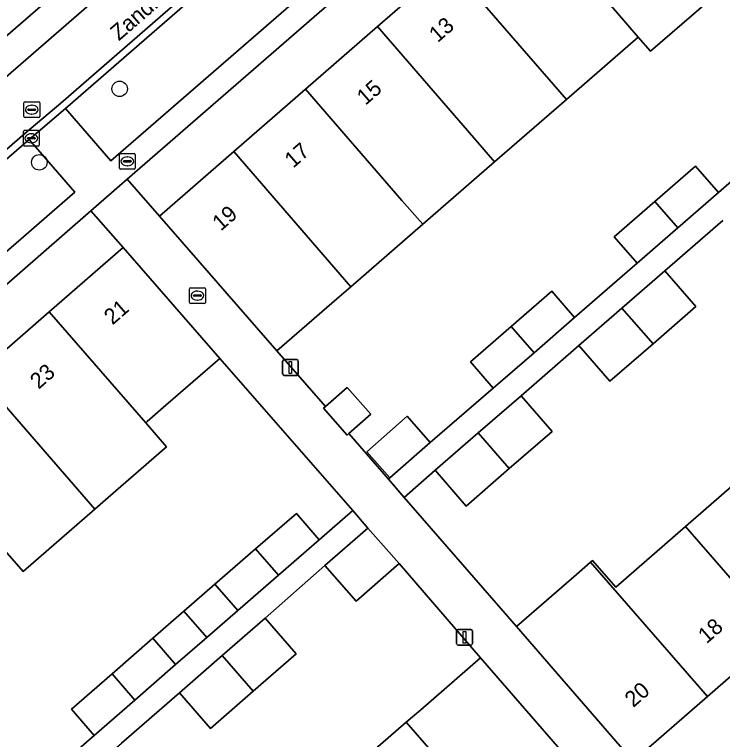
# Model space of a CAD drawing. Extents: x 155887 to 156869, y 383880 to 384678.
# Drawn here: x 156410.69 to 156455.35, y 384008.68 to 384054.39 of the extents above; entities that cross this region are included whole.
import ezdxf

# ---------------------------------------------------------------- set-up
doc = ezdxf.new("R2010")
doc.units = 0
for name, color, linetype in [('IMGEO_Boom', 7, 'Continuous'), ('IMGEO_Brandkraan', 7, 'Continuous'), ('IMGEO_Erf', 7, 'Continuous'), ('IMGEO_Kolk', 7, 'Continuous'), ('IMGEO_Lichtmast', 7, 'Continuous'), ('IMGEO_Openbare_ruimte_label', 7, 'Continuous'), ('IMGEO_Pand', 7, 'Continuous'), ('IMGEO_Pand_nummerreeks', 7, 'Continuous'), ('IMGEO_Parkeervlak_open', 7, 'Continuous'), ('IMGEO_Rijbaan_lokaal_gesloten', 7, 'Continuous'), ('IMGEO_Rijbaan_lokaal_open', 7, 'Continuous'), ('IMGEO_Rioolput', 7, 'Continuous'), ('IMGEO_Voetpad_open', 7, 'Continuous')]:
    doc.layers.add(name, color=color, linetype=linetype)

msp = doc.modelspace()

# ---------------------------------------------------------------- linework, layer by layer
at = {"layer": 'IMGEO_Boom'}
for centre in [(156417.316, 384049.703), (156412.249, 384045.068)]:
    msp.add_circle(centre, 0.489, dxfattribs=at)
at = {"layer": 'IMGEO_Brandkraan'}
for p, q in [((156417.303, 384044.707), (156417.303, 384045.559)), ((156417.378, 384045.633), (156418.23, 384045.633)), ((156417.791, 384045.413), (156417.816, 384045.413)), ((156418.304, 384045.559), (156418.304, 384044.707)), ((156417.562, 384045.127), (156417.562, 384045.139)), ((156418, 384045.09), (156417.602, 384045.09)), ((156417.605, 384045.176), (156418.003, 384045.176)), ((156417.814, 384044.853), (156417.789, 384044.853)), ((156418.046, 384045.139), (156418.046, 384045.127)), ((156418.23, 384044.633), (156417.378, 384044.633))]:
    msp.add_line(p, q, dxfattribs=at)
for points in [[(156417.303, 384044.707), (156417.303, 384045.559)], [(156417.378, 384045.633), (156418.23, 384045.633)], [(156418.304, 384045.559), (156418.304, 384044.707)], [(156418.23, 384044.633), (156417.378, 384044.633)]]:
    msp.add_lwpolyline(points, dxfattribs=at)
for centre, radius, start, end in [((156417.38, 384045.557), 0.0765, 91.552, 178.448), ((156417.38, 384045.557), 0.0765, 91.552, 178.448), ((156418.228, 384045.557), 0.0765, 1.552, 88.448), ((156418.228, 384045.557), 0.0765, 1.552, 88.448), ((156417.602, 384045.136), 0.0403, 85.8775, 175.7526), ((156417.599, 384045.126), 0.0366, 178.938, 274.7102), ((156418.003, 384045.133), 0.043, 264.8664, 352.4533), ((156418.007, 384045.138), 0.0386, 1.7309, 96.639), ((156417.38, 384044.709), 0.0765, 181.552, 268.448), ((156417.38, 384044.709), 0.0765, 181.552, 268.448), ((156418.228, 384044.709), 0.0765, 271.552, 358.448), ((156418.228, 384044.709), 0.0765, 271.552, 358.448)]:
    msp.add_arc(centre, radius, start, end, dxfattribs=at)
for centre, major_axis, ratio, start_param, end_param in [((156417.79, 384045.133), (-0.387, 0.002), 0.722429, 4.712389, 7.853982), ((156417.815, 384045.133), (-0.39, 0.002), 0.717154, 1.570796, 4.712389)]:
    msp.add_ellipse(centre, major_axis=major_axis, ratio=ratio, start_param=start_param, end_param=end_param, dxfattribs=at)
at = {"layer": 'IMGEO_Erf'}
for points in [[(156410.122, 384052.983), (156447.142, 384085.078), (156444.873, 384087.686), (156442.019, 384085.204), (156443.695, 384083.269), (156440.298, 384080.316), (156436.883, 384077.347), (156435.201, 384079.289), (156432.554, 384076.982), (156429.802, 384074.584), (156431.483, 384072.642), (156428.134, 384069.735), (156424.65, 384066.712), (156422.968, 384068.654), (156420.152, 384066.214), (156417.553, 384063.962), (156419.235, 384062.02), (156415.892, 384059.117), (156412.427, 384056.109), (156410.745, 384058.051), (156407.867, 384055.552)], [(156447.16, 384065.423), (156451.688, 384069.356), (156456.231, 384073.303), (156460.743, 384077.222), (156465.403, 384081.27), (156463.383, 384083.579), (156417.787, 384044.012), (156419.831, 384041.682), (156424.521, 384045.756), (156429.049, 384049.689), (156433.577, 384053.623), (156438.104, 384057.556), (156442.032, 384060.968), (156442.633, 384061.49)], [(156495.285, 384046.946), (156490.613, 384042.883), (156486.087, 384038.947), (156481.56, 384035.01), (156477.034, 384031.074), (156472.507, 384027.137), (156467.98, 384023.2), (156463.453, 384019.263), (156458.927, 384015.327), (156454.4, 384011.39), (156449.718, 384007.318), (156452.547, 384004.012), (156498.182, 384043.649)]]:
    msp.add_lwpolyline(points, close=True, dxfattribs=at)
for points in [[(156455.377, 384056.039), (156450.81, 384052.073), (156450.035, 384052.966), (156445.504, 384049.033), (156440.967, 384045.095), (156436.437, 384041.162), (156431.908, 384037.23), (156431.017, 384036.457), (156427.241, 384033.179), (156430.298, 384029.666), (156431.679, 384030.883), (156433.17, 384029.191), (156431.779, 384027.965), (156434.278, 384025.093), (156434.364, 384025.168), (156432.912, 384026.824), (156435.467, 384029.065), (156436.918, 384027.412), (156440.892, 384030.829), (156439.451, 384032.487), (156442.019, 384034.719), (156444.576, 384036.941), (156446.017, 384035.283), (156449.964, 384038.713), (156448.523, 384040.371), (156451.089, 384042.6), (156453.648, 384044.824), (156455.089, 384043.166), (156459.013, 384046.577)], [(156408.347, 384031.713), (156412.874, 384035.649), (156417.543, 384039.709), (156415.505, 384042.009), (156388.106, 384018.114)], [(156455.367, 384041.408), (156451.707, 384038.228), (156453.668, 384035.971), (156450.967, 384033.625), (156448.249, 384031.263), (156446.288, 384033.52), (156442.644, 384030.353), (156444.599, 384028.103), (156441.899, 384025.757), (156439.188, 384023.401), (156437.233, 384025.651), (156435.275, 384023.947), (156442.364, 384015.801), (156446.137, 384019.082), (156447.03, 384019.86), (156447.155, 384019.968), (156448.618, 384018.285), (156453.023, 384022.116), (156457.55, 384026.053)], [(156411.795, 384005.532), (156415.72, 384008.941), (156414.278, 384010.601), (156416.842, 384012.828), (156419.41, 384015.059), (156421.372, 384016.764), (156423.334, 384018.468), (156425.898, 384020.695), (156428.466, 384022.926), (156429.908, 384021.266), (156432.019, 384023.109), (156423.638, 384032.71), (156420.241, 384029.754), (156419.06, 384028.727), (156418.97, 384028.649), (156420.284, 384027.141), (156416.601, 384023.936), (156415.759, 384023.203), (156411.235, 384019.266), (156409.922, 384020.774)], [(156430.874, 384005.835), (156435.4, 384009.769), (156436.309, 384010.559), (156440.083, 384013.839), (156434.944, 384019.77), (156432.24, 384017.398), (156430.265, 384019.648), (156426.497, 384016.326), (156428.453, 384014.075), (156425.747, 384011.723), (156423.044, 384009.375), (156421.088, 384011.626), (156417.445, 384008.459)]]:
    msp.add_lwpolyline(points, dxfattribs=at)
at = {"layer": 'IMGEO_Kolk'}
for p, q in [((156411.248, 384046.161), (156411.248, 384047.013)), ((156411.323, 384047.087), (156412.175, 384047.087)), ((156411.736, 384046.867), (156411.761, 384046.867)), ((156412.249, 384047.013), (156412.249, 384046.161)), ((156411.507, 384046.581), (156411.507, 384046.593)), ((156411.945, 384046.544), (156411.547, 384046.544)), ((156411.55, 384046.63), (156411.948, 384046.63)), ((156411.759, 384046.307), (156411.734, 384046.307)), ((156411.991, 384046.593), (156411.991, 384046.581)), ((156412.175, 384046.087), (156411.323, 384046.087)), ((156421.727, 384036.24), (156421.727, 384037.092)), ((156421.802, 384037.166), (156422.654, 384037.166)), ((156422.728, 384037.092), (156422.728, 384036.24)), ((156421.986, 384036.66), (156421.986, 384036.672)), ((156422.424, 384036.623), (156422.026, 384036.623)), ((156422.029, 384036.709), (156422.427, 384036.709)), ((156422.215, 384036.946), (156422.24, 384036.946)), ((156422.47, 384036.672), (156422.47, 384036.66)), ((156422.654, 384036.166), (156421.802, 384036.166)), ((156422.238, 384036.386), (156422.213, 384036.386))]:
    msp.add_line(p, q, dxfattribs=at)
for points in [[(156411.248, 384046.161), (156411.248, 384047.013)], [(156411.323, 384047.087), (156412.175, 384047.087)], [(156412.249, 384047.013), (156412.249, 384046.161)], [(156412.175, 384046.087), (156411.323, 384046.087)], [(156421.727, 384036.24), (156421.727, 384037.092)], [(156421.802, 384037.166), (156422.654, 384037.166)], [(156422.728, 384037.092), (156422.728, 384036.24)], [(156422.654, 384036.166), (156421.802, 384036.166)]]:
    msp.add_lwpolyline(points, dxfattribs=at)
for centre, radius, start, end in [((156411.325, 384047.011), 0.0765, 91.552, 178.448), ((156411.325, 384047.011), 0.0765, 91.552, 178.448), ((156412.173, 384047.011), 0.0765, 1.552, 88.448), ((156412.173, 384047.011), 0.0765, 1.552, 88.448), ((156411.547, 384046.59), 0.0403, 85.8775, 175.7526), ((156411.544, 384046.58), 0.0366, 178.938, 274.7102), ((156411.948, 384046.587), 0.043, 264.8664, 352.4533), ((156411.952, 384046.592), 0.0386, 1.7309, 96.639), ((156411.325, 384046.163), 0.0765, 181.552, 268.448), ((156411.325, 384046.163), 0.0765, 181.552, 268.448), ((156412.173, 384046.163), 0.0765, 271.552, 358.448), ((156412.173, 384046.163), 0.0765, 271.552, 358.448), ((156421.804, 384037.09), 0.0765, 91.552, 178.448), ((156421.804, 384037.09), 0.0765, 91.552, 178.448), ((156422.652, 384037.09), 0.0765, 1.552, 88.448), ((156422.652, 384037.09), 0.0765, 1.552, 88.448), ((156422.026, 384036.669), 0.0403, 85.8775, 175.7526), ((156422.023, 384036.659), 0.0366, 178.938, 274.7102), ((156422.427, 384036.666), 0.043, 264.8664, 352.4533), ((156422.431, 384036.671), 0.0386, 1.7309, 96.639), ((156421.804, 384036.242), 0.0765, 181.552, 268.448), ((156421.804, 384036.242), 0.0765, 181.552, 268.448), ((156422.652, 384036.242), 0.0765, 271.552, 358.448), ((156422.652, 384036.242), 0.0765, 271.552, 358.448)]:
    msp.add_arc(centre, radius, start, end, dxfattribs=at)
for centre, major_axis, ratio, start_param, end_param in [((156411.735, 384046.587), (-0.387, 0.002), 0.722429, 4.712389, 7.853982), ((156411.76, 384046.587), (-0.39, 0.002), 0.717154, 1.570796, 4.712389), ((156422.214, 384036.666), (-0.387, 0.002), 0.722429, 4.712389, 7.853982), ((156422.239, 384036.666), (-0.39, 0.002), 0.717154, 1.570796, 4.712389)]:
    msp.add_ellipse(centre, major_axis=major_axis, ratio=ratio, start_param=start_param, end_param=end_param, dxfattribs=at)
at = {"layer": 'IMGEO_Lichtmast'}
for p, q in [((156427.6, 384031.736), (156427.6, 384032.536)), ((156427.6, 384032.536), (156427.6, 384031.736)), ((156427.7, 384032.636), (156428.49, 384032.636)), ((156428.49, 384032.636), (156427.7, 384032.636)), ((156428.59, 384032.536), (156428.59, 384031.736)), ((156428.59, 384031.736), (156428.59, 384032.536)), ((156428.49, 384031.636), (156427.7, 384031.636)), ((156427.7, 384031.636), (156428.49, 384031.636)), ((156438.678, 384015.623), (156439.468, 384015.623)), ((156439.468, 384015.623), (156438.678, 384015.623)), ((156438.578, 384014.723), (156438.578, 384015.523)), ((156438.578, 384015.523), (156438.578, 384014.723)), ((156439.568, 384015.523), (156439.568, 384014.723)), ((156439.568, 384014.723), (156439.568, 384015.523)), ((156439.468, 384014.623), (156438.678, 384014.623)), ((156438.678, 384014.623), (156439.468, 384014.623))]:
    msp.add_line(p, q, dxfattribs=at)
for points in [[(156428.02, 384032.511), (156428.17, 384032.511), (156428.17, 384031.761), (156428.02, 384031.761), (156428.02, 384032.511)], [(156438.998, 384015.498), (156439.148, 384015.498), (156439.148, 384014.748), (156438.998, 384014.748), (156438.998, 384015.498)]]:
    msp.add_lwpolyline(points, dxfattribs=at)
for centre, start, end in [((156427.7, 384032.536), 90, 180), ((156427.7, 384032.536), 90, 180), ((156428.49, 384032.536), 0, 90), ((156428.49, 384032.536), 360, 90), ((156427.7, 384031.736), 180, 270), ((156427.7, 384031.736), 180, 270), ((156428.49, 384031.736), 270, 0), ((156428.49, 384031.736), 270, 0), ((156438.678, 384015.523), 90, 180), ((156438.678, 384015.523), 90, 180), ((156439.468, 384015.523), 0, 90), ((156439.468, 384015.523), 360, 90), ((156438.678, 384014.723), 180, 270), ((156438.678, 384014.723), 180, 270), ((156439.468, 384014.723), 270, 0), ((156439.468, 384014.723), 270, 0)]:
    msp.add_arc(centre, 0.1, start, end, dxfattribs=at)
at = {"layer": 'IMGEO_Pand'}
for points in [[(156447.16, 384065.423), (156442.633, 384061.49), (156448.724, 384054.476), (156450.035, 384052.966), (156450.81, 384052.073), (156455.377, 384056.039), (156454.5, 384056.972), (156453.253, 384058.408), (156452.773, 384058.961)], [(156442.633, 384061.49), (156442.032, 384060.968), (156438.104, 384057.556), (156445.504, 384049.033), (156450.035, 384052.966), (156448.724, 384054.476)], [(156438.104, 384057.556), (156433.577, 384053.623), (156439.658, 384046.606), (156440.967, 384045.095), (156445.504, 384049.033)], [(156433.577, 384053.623), (156429.049, 384049.689), (156435.128, 384042.673), (156436.437, 384041.162), (156440.967, 384045.095), (156439.658, 384046.606)], [(156429.049, 384049.689), (156424.521, 384045.756), (156431.908, 384037.23), (156436.437, 384041.162), (156435.128, 384042.673)], [(156431.908, 384037.23), (156424.521, 384045.756), (156419.831, 384041.682), (156427.241, 384033.179), (156431.017, 384036.457)], [(156451.089, 384042.6), (156452.529, 384040.942), (156455.089, 384043.166), (156453.648, 384044.824)], [(156451.089, 384042.6), (156448.523, 384040.371), (156449.964, 384038.713), (156452.529, 384040.942)], [(156417.543, 384039.709), (156412.874, 384035.649), (156418.97, 384028.649), (156419.06, 384028.727), (156420.241, 384029.754), (156423.638, 384032.71)], [(156449.006, 384035.881), (156450.967, 384033.625), (156453.668, 384035.971), (156451.707, 384038.228)], [(156442.019, 384034.719), (156443.458, 384033.059), (156446.017, 384035.283), (156444.576, 384036.941)], [(156449.006, 384035.881), (156446.288, 384033.52), (156448.249, 384031.263), (156450.967, 384033.625)], [(156412.874, 384035.649), (156408.347, 384031.713), (156415.759, 384023.203), (156416.601, 384023.936), (156420.284, 384027.141), (156418.97, 384028.649)], [(156442.019, 384034.719), (156439.451, 384032.487), (156440.892, 384030.829), (156443.458, 384033.059)], [(156408.347, 384031.713), (156403.822, 384027.778), (156409.922, 384020.774), (156411.235, 384019.266), (156415.759, 384023.203)], [(156430.298, 384029.666), (156430.18, 384029.562), (156431.671, 384027.87), (156431.779, 384027.965), (156433.17, 384029.191), (156431.679, 384030.883)], [(156439.942, 384028.005), (156441.899, 384025.757), (156444.599, 384028.103), (156442.644, 384030.353)], [(156434.364, 384025.168), (156436.918, 384027.412), (156435.467, 384029.065), (156432.912, 384026.824)], [(156439.942, 384028.005), (156437.233, 384025.651), (156439.188, 384023.401), (156441.899, 384025.757)], [(156458.927, 384015.327), (156463.453, 384019.263), (156457.55, 384026.053), (156453.023, 384022.116)], [(156427.342, 384019.037), (156429.908, 384021.266), (156428.466, 384022.926), (156425.898, 384020.695)], [(156434.944, 384019.77), (156432.98, 384022.008), (156430.265, 384019.648), (156432.24, 384017.398)], [(156458.927, 384015.327), (156453.023, 384022.116), (156448.618, 384018.285), (156447.155, 384019.968), (156447.03, 384019.86), (156454.4, 384011.39)], [(156427.342, 384019.037), (156425.898, 384020.695), (156423.334, 384018.468), (156424.776, 384016.808)], [(156447.03, 384019.86), (156446.137, 384019.082), (156442.364, 384015.801), (156449.718, 384007.318), (156454.4, 384011.39)], [(156423.334, 384018.468), (156421.372, 384016.764), (156422.814, 384015.103), (156424.776, 384016.808)], [(156421.372, 384016.764), (156419.41, 384015.059), (156420.852, 384013.399), (156422.814, 384015.103)], [(156425.747, 384011.723), (156428.453, 384014.075), (156426.497, 384016.326), (156423.788, 384013.972)], [(156416.842, 384012.828), (156418.286, 384011.17), (156420.852, 384013.399), (156419.41, 384015.059)], [(156425.747, 384011.723), (156423.788, 384013.972), (156421.088, 384011.626), (156423.044, 384009.375)], [(156442.777, 384001.297), (156447.442, 384005.351), (156440.083, 384013.839), (156436.309, 384010.559), (156435.4, 384009.769)], [(156416.842, 384012.828), (156414.278, 384010.601), (156415.72, 384008.941), (156418.286, 384011.17)], [(156438.193, 383997.312), (156441.285, 384000), (156442.777, 384001.297), (156435.4, 384009.769), (156430.874, 384005.835), (156435.955, 384000)]]:
    msp.add_lwpolyline(points, close=True, dxfattribs=at)
at = {"layer": 'IMGEO_Parkeervlak_open'}
msp.add_lwpolyline([(156413.906, 384048.462), (156416.764, 384045.168), (156462.406, 384084.734), (156459.54, 384088.037), (156458.91, 384087.552)], close=True, dxfattribs=at)
for points in [[(156414.489, 384043.181), (156411.601, 384046.501), (156373.103, 384013.064)], [(156366.002, 384005.454), (156368.129, 384002.924), (156414.489, 384043.181)]]:
    msp.add_lwpolyline(points, dxfattribs=at)
at = {"layer": 'IMGEO_Rijbaan_lokaal_gesloten'}
for points in [[(156372.8, 384013.411), (156411.334, 384046.878), (156413.606, 384048.808), (156458.618, 384087.909), (156458.873, 384088.104), (156452.602, 384095.338)], [(156449.055, 384084.789), (156448.166, 384083.918), (156444.013, 384079.846), (156371.934, 384017.308)]]:
    msp.add_lwpolyline(points, dxfattribs=at)
at = {"layer": 'IMGEO_Rijbaan_lokaal_open'}
for points in [[(156452.947, 384095.643), (156452.602, 384095.338), (156458.873, 384088.104), (156458.618, 384087.909), (156413.606, 384048.808), (156411.334, 384046.878), (156372.8, 384013.411)], [(156373.103, 384013.064), (156411.601, 384046.501), (156413.906, 384048.462), (156458.91, 384087.552), (156459.54, 384088.037), (156452.947, 384095.643)]]:
    msp.add_lwpolyline(points, dxfattribs=at)
at = {"layer": 'IMGEO_Rioolput'}
for p, q in [((156411.277, 384047.961), (156411.277, 384048.813)), ((156411.352, 384048.887), (156412.204, 384048.887)), ((156411.765, 384048.667), (156411.79, 384048.667)), ((156412.278, 384048.813), (156412.278, 384047.961)), ((156411.536, 384048.381), (156411.536, 384048.393)), ((156411.974, 384048.344), (156411.576, 384048.344)), ((156411.579, 384048.43), (156411.977, 384048.43)), ((156411.788, 384048.107), (156411.763, 384048.107)), ((156412.02, 384048.393), (156412.02, 384048.381)), ((156412.204, 384047.887), (156411.352, 384047.887))]:
    msp.add_line(p, q, dxfattribs=at)
for points in [[(156411.277, 384047.961), (156411.277, 384048.813)], [(156411.352, 384048.887), (156412.204, 384048.887)], [(156412.278, 384048.813), (156412.278, 384047.961)], [(156412.204, 384047.887), (156411.352, 384047.887)]]:
    msp.add_lwpolyline(points, dxfattribs=at)
for centre, radius, start, end in [((156411.354, 384048.811), 0.0765, 91.552, 178.448), ((156411.354, 384048.811), 0.0765, 91.552, 178.448), ((156412.202, 384048.811), 0.0765, 1.552, 88.448), ((156412.202, 384048.811), 0.0765, 1.552, 88.448), ((156411.576, 384048.39), 0.0403, 85.8775, 175.7526), ((156411.573, 384048.38), 0.0366, 178.938, 274.7102), ((156411.977, 384048.387), 0.043, 264.8664, 352.4533), ((156411.981, 384048.392), 0.0386, 1.7309, 96.639), ((156411.354, 384047.963), 0.0765, 181.552, 268.448), ((156411.354, 384047.963), 0.0765, 181.552, 268.448), ((156412.202, 384047.963), 0.0765, 271.552, 358.448), ((156412.202, 384047.963), 0.0765, 271.552, 358.448)]:
    msp.add_arc(centre, radius, start, end, dxfattribs=at)
for centre, major_axis, ratio, start_param, end_param in [((156411.764, 384048.387), (-0.387, 0.002), 0.722429, 4.712389, 7.853982), ((156411.789, 384048.387), (-0.39, 0.002), 0.717154, 1.570796, 4.712389)]:
    msp.add_ellipse(centre, major_axis=major_axis, ratio=ratio, start_param=start_param, end_param=end_param, dxfattribs=at)
at = {"layer": 'IMGEO_Voetpad_open'}
for points in [[(156444.013, 384079.846), (156448.166, 384083.918), (156447.142, 384085.078), (156410.122, 384052.983), (156407.826, 384050.978), (156406.195, 384049.568), (156362.61, 384011.694), (156360.938, 384011.241), (156362.105, 384009.899), (156362.712, 384010.226), (156363.265, 384010.638)], [(156371.934, 384017.308), (156444.013, 384079.846)], [(156459.013, 384046.577), (156455.089, 384043.166), (156452.529, 384040.942), (156449.964, 384038.713), (156446.017, 384035.283), (156443.458, 384033.059), (156440.892, 384030.829), (156436.918, 384027.412), (156434.364, 384025.168), (156434.278, 384025.093), (156435.275, 384023.947), (156437.233, 384025.651), (156439.942, 384028.005), (156442.644, 384030.353), (156446.288, 384033.52), (156449.006, 384035.881), (156451.707, 384038.228), (156455.367, 384041.408)]]:
    msp.add_lwpolyline(points, dxfattribs=at)
for points in [[(156463.383, 384083.579), (156462.406, 384084.734), (156416.764, 384045.168), (156413.906, 384048.462), (156411.601, 384046.501), (156414.489, 384043.181), (156368.129, 384002.924), (156369.161, 384001.79), (156373.325, 384005.318), (156382.174, 384012.981), (156388.106, 384018.114), (156415.505, 384042.009), (156417.787, 384044.012)], [(156435.275, 384023.947), (156434.278, 384025.093), (156431.779, 384027.965), (156431.671, 384027.87), (156430.18, 384029.562), (156430.298, 384029.666), (156427.241, 384033.179), (156419.831, 384041.682), (156417.787, 384044.012), (156415.505, 384042.009), (156417.543, 384039.709), (156423.638, 384032.71), (156432.019, 384023.109), (156432.98, 384022.008), (156434.944, 384019.77), (156440.083, 384013.839), (156447.442, 384005.351), (156450.32, 384002.104), (156452.547, 384004.012), (156449.718, 384007.318), (156442.364, 384015.801)], [(156421.088, 384011.626), (156423.788, 384013.972), (156426.497, 384016.326), (156430.265, 384019.648), (156432.98, 384022.008), (156432.019, 384023.109), (156429.908, 384021.266), (156427.342, 384019.037), (156424.776, 384016.808), (156422.814, 384015.103), (156420.852, 384013.399), (156418.286, 384011.17), (156415.72, 384008.941), (156411.795, 384005.532), (156409.229, 384003.303), (156406.663, 384001.074), (156404.537, 383999.225), (156405.52, 383998.094), (156407.713, 384000), (156408.235, 384000.454), (156410.126, 384002.097), (156412.052, 384003.771), (156414.691, 384006.065), (156417.445, 384008.459)]]:
    msp.add_lwpolyline(points, close=True, dxfattribs=at)

# ---------------------------------------------------------------- texts
at = {"layer": 'IMGEO_Openbare_ruimte_label'}
msp.add_text('Zandroos', height=1, rotation=40.9433, dxfattribs=at).set_placement((156417.27, 384052.692))
at = {"layer": 'IMGEO_Pand_nummerreeks'}
for s, rotation, p in [('13', 40.9779, (156437.378, 384052.579)), ('15', 40.9779, (156432.821, 384048.621)), ('17', 40.9779, (156428.264, 384044.662)), ('19', 40.9806, (156423.705, 384040.703)), ('21', 41.0066, (156416.869, 384034.777)), ('23', 41.0066, (156412.207, 384030.724)), ('18', 41.0123, (156454.346, 384014.682)), ('20', 41.0123, (156449.721, 384010.66))]:
    msp.add_text(s, height=1, rotation=rotation, dxfattribs=at).set_placement(p)

doc.saveas('drawing.dxf')
